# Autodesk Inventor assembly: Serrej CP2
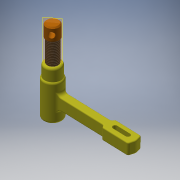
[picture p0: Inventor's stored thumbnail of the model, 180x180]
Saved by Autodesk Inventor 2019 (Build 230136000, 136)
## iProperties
Created: 2019-02
Part Number: Serrej CP2
Material: Générique
Document SubType Name: Assembly
Designer: si-nd67
Author: si-nd67
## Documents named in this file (3)
- E:\ECAM\serrejointsw\Serrej CP2.iam
- E:\ECAM\serrejointsw\Serrej-ACp.iam
- E:\ECAM\serrejointsw\Vis de manoeuvre14.ipt
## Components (2 placed, 2 different names)
1. Serrej-ACp:1 [sub-assembly] — Placage:1, Placage:2
2. Vis de manoeuvre14:1 — Placage:1, Placage:2
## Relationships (2: Mate 2)
- Placage:1 [Mate]: Serrej-ACp:1 ↔ Vis de manoeuvre14:1
- Placage:2 [Mate]: Serrej-ACp:1 ↔ Vis de manoeuvre14:1
